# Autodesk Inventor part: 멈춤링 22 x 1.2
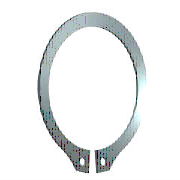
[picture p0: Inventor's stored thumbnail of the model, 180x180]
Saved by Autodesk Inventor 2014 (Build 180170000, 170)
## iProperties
IsCustomPart: 0
Created: 2015-11
Part Number: 멈춤링 22 x 1.2
Material: 스테인리스강
Description: 리테이닝 링(C형)
Document SubType Name: Modeling
Standard: KS B 1336
Designer: mdu
Standards Organization: KS
Language: ko-KR
Size Designation: 22 x 1.2
Categories: <MemberInstance><Categories><Category DisplayName="샤프트 부품" InternalName="7f7aeb1f-a693-4053-b835-cee3144e0d98" Mnemonic="SHFT"><Category DisplayName="써클립" Inter
Density: 8.08 g/cm^3
Appearance: 반광택
Mass: 1.87978 g
Surface Area: 5.91219 cm^2
Volume: 0.232646 cm^3
Author: mdu
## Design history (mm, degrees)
sketch "스케치1"
  geometry: L1 (-6, 0)-(6, 0) reference; L2 (0, 20.189)-(0, -80.536) reference; L3 (-48.09, 0)-(48.09, 0) reference; L4 (-0.5, -21.488)-(-0.5, -25.588); L5 (-0.5, -6.54)-(-0.5, -13.29); L6 (-2.795, 2.7)-(3.672, 2.7); L7 (0.5, -6.54)-(0.5, -13.29); L8 (0.5, -21.488)-(0.5, -25.588); C1 r 1 at (-2, -23.437); C2 r 1 at (2, -23.437); A1 r 10.5 centre (0, -11) between (0.5, -21.488) and (-0.5, -21.488); A2 r 13.025 centre (0, -10.325) between (5.149, -22.289) and (-5.149, -22.289); A3 r 14.597 centre (0, -11) between (-2.318, -25.411) and (-0.5, -25.588); A4 r 2 centre (-2, -23.437) between (-3.97, -23.781) and (-2.318, -25.411); A5 r 2 centre (-5.94, -24.126) between (-3.97, -23.781) and (-5.149, -22.289); A6 r 2 centre (5.94, -24.126) between (5.149, -22.289) and (3.97, -23.781); A7 r 2 centre (2, -23.437) between (2.318, -25.411) and (3.97, -23.781); A8 r 14.597 centre (0, -11) between (0.5, -25.588) and (2.318, -25.411)
  constraints: 16 point on circle, 12 end point, 10 centre point, 9 symmetric about line, 5 point on line, 4 tangent, 3 coincident, 2 horizontal, 1 perpendicular, 1 vertical, 5 other
  dimensions: "d0" = 21 diameter of A1 (= ND); "d1" = 4.1 distance of L4.end L4.start (= SRB2); "d6" = 0.5 distance between parallel lines of L2 L5 (= 0.25 x SD5); "d7" = 2.7 distance between parallel lines of L6 L3 (= SRB1); "d8" = 0.675 distance of A1.centre A2.centre (= 0.25 x SRB1); "d9" = 2 radius of A4 (= SD5); "d10" = 2 radius of A5 (= SD5); "d11" = 1.5 distance from line of L4 A4.centre (= 0.75 x SD5); "d12" = 2 diameter of C1 (= SD5); "d13" = 2 diameter of C2 (= SD5); "d14" = 11 distance from line of A1.centre L1 (= 0.5 x WD)
extrude "본체" new body sketch "스케치1" distance "d2" = 1.2 (= SD); taper "d3" = 0 deg
workaxis "Work Axis1"
workplane "Work Plane1"
body "Solid1"
other parameters: "WD" = 22 (= WDMIN) [user parameter; used in 1 equation term], "SD" = 1.2 [user parameter; used in 1 equation term], "SRB1" = 2.7 [user parameter; used in 2 equation terms], "ND" = 21 [user parameter; used in 1 equation term], "SRB2" = 4.1 [user parameter; used in 1 equation term], "SD5" = 2 [user parameter; used in 6 equation terms], "d15" = 0, "d16" = 0, "d17" = 0, "d41" = 0, "d42" = 0, "WDMIN" = 22 [user parameter; used in 1 equation term], "SD3" = 20.5 [user parameter], "WDMAX" = 24 [user parameter]
